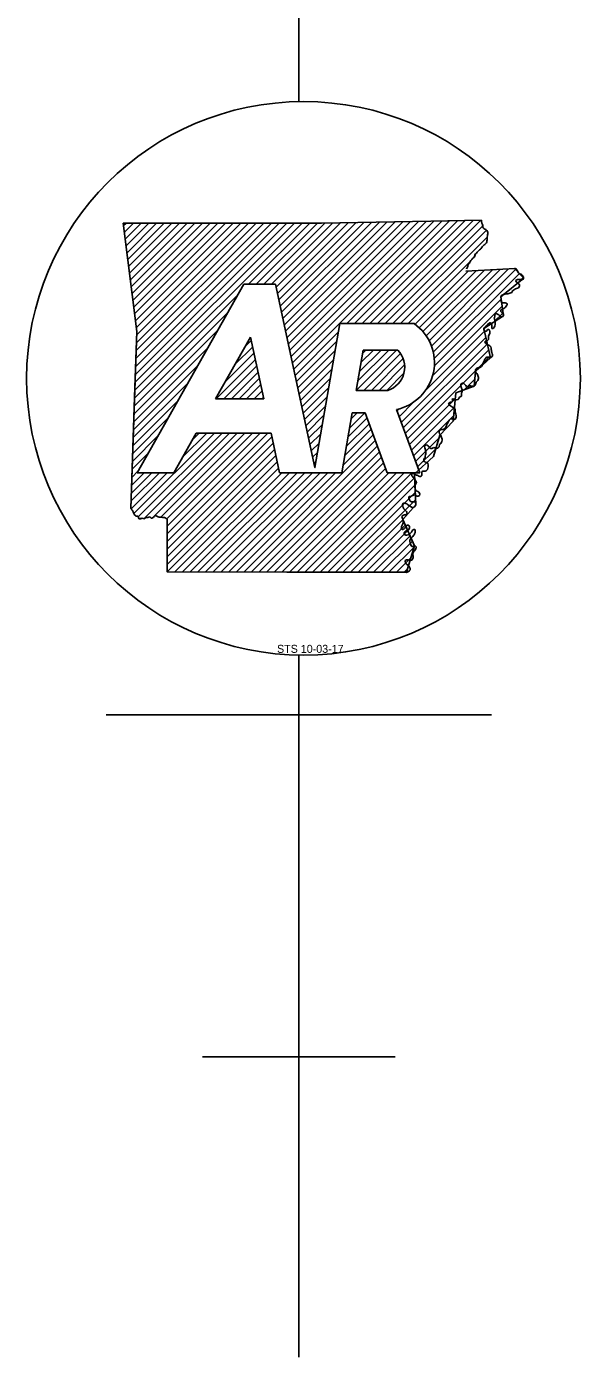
# Model space of a CAD drawing. Extents: x 1370130 to 1380143, y 377636 to 380256.
# Drawn here: x 1377791.3 to 1377833.4, y 379091.1 to 379192.1 of the extents above; entities that cross this region are included whole.
import ezdxf

# ---------------------------------------------------------------- set-up
doc = ezdxf.new("R2010")
doc.units = 0
for name, color, linetype in [('R_Draft', 7, 'Continuous'), ('R_Exist Surface', 7, 'Continuous'), ('R_Water Annot', 7, 'Continuous')]:
    doc.layers.add(name, color=color, linetype=linetype)

# ---------------------------------------------------------------- blocks, each defined once
blk = doc.blocks.new('NORTH ARROW VICINITY MAP')
at = {"layer": 'R_Draft'}
for p, q in [((0, 30.512), (0, 72.554)), ((-3.931, 21.495), (-1.338, 26.073)), ((-1.338, 26.073), (-0.568, 26.073)), ((0.996, 25.118), (2.796, 25.118)), ((-2.024, 23.292), (-1.176, 24.79)), ((1.557, 24.472), (2.402, 24.472)), ((-2.024, 23.292), (-0.855, 23.292)), ((1.386, 23.495), (2.158, 23.495)), ((2.366, 23.029), (2.932, 21.495)), ((1.604, 22.951), (1.292, 22.951)), ((2.142, 21.495), (1.604, 22.951)), ((-2.497, 22.456), (-3.041, 21.495)), ((-0.676, 22.456), (-2.497, 22.456)), ((-3.041, 21.495), (-3.931, 21.495)), ((1.038, 21.495), (-0.471, 21.495)), ((2.932, 21.495), (2.142, 21.495)), ((0, 0), (0, 17.063)), ((-4.681, 15.613), (4.68, 15.613)), ((-2.341, 7.3), (2.34, 7.3))]:
    blk.add_line(p, q, dxfattribs=at)
for points in [[(-4.267, 27.557), (-1.704, 27.556), (0.548, 27.561), (3.201, 27.602), (4.431, 27.631)], [(-4.267, 27.558), (-1.703, 27.556), (0.547, 27.561), (3.201, 27.602), (4.431, 27.631)], [(-4.081, 20.621), (-3.939, 24.923), (-4.267, 27.558)], [(-3.984, 23.572), (-3.939, 24.923), (-4.267, 27.557)], [(5.237, 26.453), (5.459, 26.221), (4.905, 25.767), (4.965, 25.308), (4.491, 24.995), (4.653, 24.289), (4.287, 23.955), (4.255, 23.593), (3.81, 23.433), (3.741, 22.748), (3.421, 22.406), (3.267, 21.891), (2.802, 21.465), (2.837, 20.714), (2.521, 20.359), (2.809, 19.714), (2.609, 19.074)], [(4.051, 26.393), (5.254, 26.455)], [(4.051, 26.394), (5.254, 26.454)], [(-0.568, 26.073), (0.385, 21.618), (0.996, 25.118)], [(-1.176, 24.79), (-0.855, 23.292)], [(1.386, 23.495), (1.557, 24.472)], [(-4.081, 20.621), (-3.984, 23.572)], [(1.292, 22.951), (1.038, 21.495)], [(-0.471, 21.495), (-0.676, 22.456)], [(2.609, 19.074), (-3.201, 19.083), (-3.205, 20.366)], [(2.609, 19.073), (-3.201, 19.083), (-3.204, 20.366)]]:
    blk.add_lwpolyline(points, dxfattribs=at)
blk.add_ellipse((0.109, 23.787), major_axis=(6.725, 0), ratio=0.999976, dxfattribs=at)
for centre, major_axis, start_param, end_param in [((2.127, 24.167), (-1.163, 0), 1.777838, 4.099264), ((1.973, 24.06), (-0.595, 0), 1.887169, 3.90762)]:
    blk.add_ellipse(centre, major_axis=major_axis, ratio=0.999987, start_param=start_param, end_param=end_param, dxfattribs=at)
for points in [[(4.431, 27.631), (4.439, 27.561), (4.46, 27.525), (4.463, 27.458), (4.491, 27.429), (4.538, 27.401), (4.578, 27.355), (4.588, 27.302), (4.575, 27.246), (4.572, 27.183), (4.566, 27.129), (4.556, 27.081), (4.518, 27.041), (4.482, 27.013), (4.449, 26.98), (4.425, 26.944), (4.384, 26.907), (4.342, 26.866), (4.308, 26.832), (4.275, 26.788), (4.259, 26.739), (4.224, 26.703), (4.195, 26.671), (4.157, 26.628), (4.138, 26.587), (4.102, 26.537), (4.093, 26.49), (4.07, 26.452), (4.068, 26.445)], [(4.431, 27.631), (4.439, 27.561), (4.461, 27.525), (4.465, 27.458), (4.491, 27.43), (4.537, 27.401), (4.579, 27.355), (4.588, 27.301), (4.576, 27.246), (4.572, 27.184), (4.566, 27.13), (4.556, 27.081), (4.518, 27.041), (4.482, 27.013), (4.449, 26.979), (4.425, 26.944), (4.384, 26.906), (4.342, 26.867), (4.309, 26.832), (4.276, 26.787), (4.26, 26.738), (4.224, 26.703), (4.195, 26.672), (4.157, 26.629), (4.138, 26.586), (4.101, 26.537), (4.094, 26.489), (4.07, 26.451), (4.068, 26.445)], [(5.237, 26.453), (5.254, 26.454), (5.308, 26.398), (5.331, 26.35), (5.367, 26.323), (5.407, 26.309), (5.437, 26.272), (5.457, 26.232), (5.446, 26.197), (5.401, 26.194), (5.352, 26.187), (5.305, 26.188), (5.266, 26.155), (5.302, 26.114), (5.348, 26.073), (5.36, 26.031), (5.335, 25.99), (5.284, 25.968), (5.235, 25.948), (5.19, 25.911), (5.169, 25.874), (5.121, 25.858), (5.07, 25.844), (5.026, 25.839), (4.975, 25.829), (4.926, 25.805), (4.906, 25.765), (4.912, 25.707), (4.91, 25.644), (4.962, 25.624), (5.008, 25.622), (5.053, 25.599), (5.048, 25.564), (5.015, 25.519), (4.975, 25.484), (4.936, 25.467), (4.899, 25.433), (4.912, 25.399), (4.945, 25.379), (4.969, 25.342), (4.965, 25.309), (4.927, 25.285), (4.886, 25.294), (4.855, 25.334), (4.821, 25.346), (4.79, 25.36), (4.756, 25.34), (4.756, 25.294), (4.744, 25.245), (4.755, 25.209), (4.768, 25.158), (4.767, 25.12), (4.755, 25.065), (4.727, 25.01), (4.697, 24.993), (4.682, 25.053), (4.677, 25.102), (4.657, 25.131), (4.632, 25.132), (4.599, 25.109), (4.563, 25.072), (4.517, 25.032), (4.49, 24.993), (4.504, 24.944), (4.539, 24.932), (4.566, 24.94), (4.58, 24.972), (4.606, 24.976), (4.632, 24.927)], [(4.632, 24.927), (4.639, 24.882), (4.612, 24.833), (4.602, 24.784), (4.606, 24.734), (4.556, 24.707), (4.512, 24.675), (4.538, 24.637), (4.586, 24.603), (4.632, 24.576), (4.662, 24.549), (4.67, 24.485), (4.678, 24.443), (4.695, 24.385), (4.701, 24.346), (4.672, 24.299), (4.639, 24.289), (4.603, 24.299), (4.563, 24.303), (4.53, 24.272), (4.506, 24.227), (4.482, 24.182), (4.463, 24.145), (4.446, 24.103), (4.412, 24.055), (4.37, 24.048), (4.319, 24.035), (4.288, 24), (4.294, 23.941), (4.322, 23.902), (4.344, 23.853), (4.359, 23.81), (4.352, 23.756), (4.33, 23.716), (4.302, 23.692), (4.288, 23.642), (4.267, 23.603), (4.249, 23.591), (4.211, 23.594), (4.169, 23.602), (4.135, 23.599), (4.102, 23.582), (4.068, 23.592), (4.033, 23.631), (4.004, 23.66), (3.972, 23.67), (3.939, 23.653), (3.934, 23.6), (3.95, 23.547), (3.964, 23.474), (3.95, 23.43), (3.944, 23.356)], [(3.944, 23.356), (3.889, 23.314), (3.864, 23.27), (3.723, 23.283), (3.727, 23.233), (3.677, 23.207), (3.632, 23.175), (3.657, 23.137), (3.705, 23.102), (3.753, 23.075), (3.783, 23.049), (3.79, 22.983), (3.799, 22.942), (3.815, 22.884), (3.821, 22.845), (3.792, 22.798), (3.759, 22.788), (3.725, 22.8), (3.683, 22.802), (3.65, 22.771), (3.626, 22.727), (3.603, 22.681), (3.585, 22.644), (3.566, 22.602), (3.533, 22.554), (3.49, 22.547), (3.439, 22.535), (3.409, 22.5), (3.414, 22.441), (3.442, 22.402), (3.464, 22.352), (3.48, 22.31), (3.473, 22.256), (3.451, 22.215), (3.422, 22.191), (3.409, 22.141), (3.388, 22.103), (3.369, 22.091), (3.332, 22.095), (3.291, 22.102), (3.256, 22.099), (3.223, 22.081), (3.188, 22.093), (3.154, 22.13), (3.125, 22.159), (3.093, 22.17), (3.059, 22.153), (3.054, 22.1), (3.07, 22.047), (3.084, 21.973), (3.07, 21.93), (3.065, 21.855)], [(3.065, 21.855), (3.061, 21.853), (3.033, 21.817), (3.049, 21.761), (3.11, 21.74), (3.139, 21.686), (3.14, 21.638), (3.12, 21.573), (3.091, 21.542), (3.036, 21.53), (2.994, 21.522), (2.987, 21.449), (2.968, 21.413), (2.935, 21.402), (2.887, 21.425), (2.858, 21.438), (2.823, 21.453), (2.779, 21.478), (2.745, 21.474), (2.755, 21.405), (2.758, 21.402), (2.797, 21.349), (2.834, 21.308), (2.851, 21.259)], [(3.065, 21.855), (3.061, 21.853), (3.033, 21.817), (3.049, 21.761), (3.11, 21.74), (3.139, 21.686), (3.14, 21.638), (3.12, 21.573), (3.091, 21.542), (3.036, 21.53), (2.994, 21.522), (2.987, 21.449), (2.968, 21.413), (2.935, 21.402), (2.887, 21.425), (2.858, 21.438), (2.823, 21.453), (2.779, 21.478), (2.745, 21.474), (2.755, 21.405), (2.758, 21.402), (2.797, 21.349), (2.834, 21.308), (2.851, 21.259)], [(2.851, 21.259), (2.836, 21.222), (2.818, 21.159), (2.823, 21.105), (2.848, 21.06), (2.885, 21.034), (2.927, 20.998), (2.924, 20.942), (2.899, 20.922), (2.843, 20.935), (2.801, 20.955), (2.765, 20.944), (2.716, 20.92), (2.679, 20.914), (2.681, 20.838), (2.729, 20.785), (2.772, 20.785), (2.822, 20.778), (2.839, 20.721), (2.81, 20.673), (2.763, 20.65), (2.703, 20.679), (2.66, 20.709), (2.618, 20.737), (2.564, 20.751), (2.533, 20.746), (2.519, 20.679), (2.544, 20.619), (2.585, 20.577), (2.623, 20.523), (2.618, 20.483), (2.589, 20.473), (2.538, 20.461), (2.508, 20.446), (2.501, 20.433), (2.516, 20.379), (2.53, 20.321), (2.53, 20.275), (2.512, 20.236), (2.486, 20.172), (2.489, 20.131), (2.508, 20.111), (2.531, 20.117), (2.564, 20.139), (2.584, 20.165), (2.602, 20.197), (2.634, 20.223), (2.675, 20.2), (2.685, 20.151), (2.662, 20.108), (2.628, 20.088), (2.588, 20.072), (2.557, 20.038), (2.564, 19.996), (2.589, 19.974), (2.648, 19.986), (2.687, 20.004), (2.71, 20.024), (2.736, 20.052), (2.75, 20.08), (2.771, 20.108), (2.808, 20.116), (2.825, 20.093), (2.818, 20.038), (2.797, 19.987), (2.766, 19.945), (2.733, 19.915), (2.692, 19.85), (2.7, 19.79), (2.716, 19.739), (2.737, 19.702), (2.776, 19.709), (2.818, 19.715), (2.843, 19.694), (2.841, 19.649), (2.81, 19.606), (2.779, 19.565), (2.763, 19.509), (2.77, 19.468), (2.77, 19.433), (2.757, 19.392), (2.735, 19.37), (2.675, 19.371), (2.614, 19.378), (2.581, 19.359), (2.588, 19.306), (2.623, 19.266), (2.649, 19.245), (2.685, 19.201), (2.701, 19.164), (2.697, 19.133), (2.674, 19.104), (2.609, 19.073)], [(2.851, 21.259), (2.836, 21.222), (2.818, 21.159), (2.823, 21.105), (2.848, 21.06), (2.885, 21.034), (2.927, 20.998), (2.924, 20.942), (2.899, 20.922), (2.843, 20.935), (2.801, 20.955), (2.765, 20.944), (2.716, 20.92), (2.679, 20.914), (2.681, 20.838), (2.729, 20.785), (2.772, 20.785), (2.822, 20.778), (2.839, 20.721), (2.81, 20.673), (2.763, 20.65), (2.703, 20.679), (2.66, 20.709), (2.618, 20.737), (2.564, 20.751), (2.533, 20.746), (2.519, 20.679), (2.544, 20.619), (2.585, 20.577), (2.623, 20.523), (2.618, 20.483), (2.589, 20.473), (2.538, 20.461), (2.508, 20.446), (2.501, 20.433), (2.516, 20.379), (2.53, 20.321), (2.53, 20.275), (2.512, 20.236), (2.486, 20.172), (2.489, 20.131), (2.508, 20.111), (2.531, 20.117), (2.564, 20.139), (2.584, 20.165), (2.602, 20.197), (2.634, 20.223), (2.675, 20.2), (2.685, 20.151), (2.662, 20.108), (2.628, 20.088), (2.588, 20.072), (2.557, 20.038), (2.564, 19.996), (2.589, 19.974), (2.648, 19.986), (2.687, 20.004), (2.71, 20.024), (2.736, 20.052), (2.75, 20.08), (2.771, 20.108), (2.808, 20.116), (2.825, 20.093), (2.818, 20.038), (2.797, 19.987), (2.766, 19.945), (2.733, 19.915), (2.692, 19.85), (2.7, 19.79), (2.716, 19.739), (2.737, 19.702), (2.776, 19.709), (2.818, 19.715), (2.843, 19.694), (2.841, 19.649), (2.81, 19.606), (2.779, 19.565), (2.763, 19.509), (2.77, 19.468), (2.77, 19.433), (2.757, 19.392), (2.735, 19.37), (2.675, 19.371), (2.614, 19.378), (2.581, 19.359), (2.588, 19.306), (2.623, 19.266), (2.649, 19.245), (2.685, 19.201), (2.701, 19.164), (2.697, 19.133), (2.674, 19.104), (2.609, 19.073)], [(-3.204, 20.366), (-3.198, 20.363), (-3.228, 20.384), (-3.27, 20.404), (-3.316, 20.407), (-3.375, 20.415), (-3.424, 20.42), (-3.474, 20.453), (-3.527, 20.419), (-3.588, 20.393), (-3.623, 20.422), (-3.669, 20.402), (-3.701, 20.413), (-3.756, 20.374), (-3.809, 20.388), (-3.846, 20.378), (-3.894, 20.379), (-3.904, 20.433), (-3.95, 20.44), (-3.99, 20.463), (-4.016, 20.518), (-4.036, 20.562), (-4.081, 20.621)], [(-3.205, 20.366), (-3.198, 20.363), (-3.228, 20.384), (-3.27, 20.404), (-3.316, 20.407), (-3.374, 20.415), (-3.423, 20.42), (-3.474, 20.453), (-3.528, 20.418), (-3.588, 20.393), (-3.623, 20.422), (-3.669, 20.403), (-3.701, 20.412), (-3.756, 20.374), (-3.809, 20.388), (-3.847, 20.377), (-3.894, 20.379), (-3.904, 20.433), (-3.95, 20.441), (-3.989, 20.463), (-4.016, 20.518), (-4.035, 20.561), (-4.081, 20.621)]]:
    blk.add_spline(points, degree=3, dxfattribs=at)
at = {"layer": 'R_Water Annot'}
for p, q in [((-4.26, 27.5), (-4.202, 27.558)), ((-4.239, 27.335), (-4.016, 27.558)), ((-4.219, 27.17), (-3.83, 27.558)), ((-4.198, 27.004), (-3.645, 27.558)), ((-4.177, 26.839), (-3.459, 27.558)), ((-4.157, 26.674), (-3.273, 27.557)), ((-4.136, 26.509), (-3.087, 27.557)), ((-4.116, 26.343), (-2.902, 27.557)), ((-4.095, 26.178), (-2.716, 27.557)), ((-4.074, 26.013), (-2.53, 27.557)), ((-4.054, 25.848), (-2.345, 27.557)), ((-4.033, 25.682), (-2.159, 27.557)), ((-4.013, 25.517), (-1.973, 27.557)), ((-3.992, 25.352), (-1.787, 27.556)), ((-3.986, 23.5), (0.075, 27.56)), ((-3.98, 23.692), (-0.112, 27.56)), ((-3.973, 23.884), (-0.298, 27.559)), ((-3.972, 25.187), (-1.601, 27.557)), ((-3.967, 24.076), (-0.484, 27.559)), ((-3.96, 24.268), (-0.67, 27.559)), ((-3.954, 24.461), (-0.857, 27.558)), ((-3.951, 25.021), (-1.415, 27.557)), ((-3.948, 24.653), (-1.043, 27.558)), ((-3.941, 24.845), (-1.229, 27.557)), ((-1.226, 26.073), (0.261, 27.561)), ((-1.04, 26.073), (0.447, 27.561)), ((-0.855, 26.073), (0.635, 27.563)), ((-0.669, 26.073), (0.823, 27.565)), ((-0.553, 26.003), (1.012, 27.568)), ((-0.52, 25.85), (1.201, 27.571)), ((-0.488, 25.697), (1.39, 27.574)), ((-0.455, 25.544), (1.578, 27.577)), ((-0.422, 25.391), (1.767, 27.58)), ((-0.389, 25.238), (1.956, 27.583)), ((-0.356, 25.085), (2.145, 27.586)), ((-0.324, 24.932), (2.333, 27.589)), ((-0.291, 24.779), (2.522, 27.592)), ((-0.258, 24.626), (2.711, 27.595)), ((-0.225, 24.473), (2.9, 27.598)), ((-0.193, 24.32), (3.088, 27.601)), ((-0.16, 24.166), (3.278, 27.604)), ((-0.127, 24.013), (3.468, 27.609)), ((1.164, 25.118), (3.658, 27.613)), ((1.35, 25.118), (3.849, 27.617)), ((1.535, 25.118), (4.039, 27.622)), ((1.721, 25.118), (4.229, 27.626)), ((1.907, 25.118), (4.419, 27.631)), ((2.093, 25.118), (4.461, 27.486)), ((2.279, 25.118), (4.551, 27.39)), ((2.465, 25.118), (4.575, 27.228)), ((2.65, 25.118), (4.15, 26.618)), ((2.819, 25.102), (4.114, 26.396)), ((2.921, 25.017), (4.31, 26.406)), ((3.011, 24.922), (4.506, 26.416)), ((3.092, 24.816), (4.701, 26.426)), ((3.161, 24.7), (4.897, 26.436)), ((3.217, 24.571), (5.093, 26.446)), ((3.26, 24.427), (5.27, 26.437)), ((3.285, 24.267), (5.356, 26.338)), ((5.274, 26.07), (5.443, 26.239)), ((-3.992, 23.307), (-1.485, 25.815)), ((3.286, 24.082), (4.913, 25.708)), ((-3.999, 23.115), (-1.727, 25.387)), ((3.248, 23.857), (4.934, 25.544)), ((4.726, 25.15), (4.956, 25.38)), ((-4.005, 22.923), (-1.97, 24.958)), ((-0.094, 23.86), (0.96, 24.915)), ((3.086, 23.51), (4.506, 24.93)), ((-1.308, 24.557), (-1.158, 24.707)), ((-0.062, 23.707), (0.921, 24.69)), ((2.48, 22.718), (4.541, 24.779)), ((2.531, 22.583), (4.575, 24.628)), ((-4.011, 22.731), (-2.213, 24.53)), ((-1.793, 23.7), (-1.093, 24.4)), ((-1.55, 24.128), (-1.125, 24.553)), ((-0.029, 23.554), (0.882, 24.465)), ((1.387, 23.495), (2.365, 24.472)), ((1.425, 23.718), (2.179, 24.472)), ((1.465, 23.943), (1.993, 24.472)), ((1.504, 24.168), (1.808, 24.472)), ((1.543, 24.394), (1.622, 24.472)), ((1.573, 23.495), (2.468, 24.39)), ((1.759, 23.495), (2.531, 24.267)), ((2.581, 22.447), (4.61, 24.476)), ((2.631, 22.311), (4.645, 24.325)), ((-4.018, 22.539), (-2.455, 24.101)), ((-2.015, 23.292), (-1.06, 24.247)), ((-1.829, 23.292), (-1.027, 24.094)), ((-1.643, 23.292), (-0.994, 23.941)), ((0.004, 23.401), (0.842, 24.24)), ((0.037, 23.248), (0.803, 24.015)), ((1.945, 23.495), (2.566, 24.115)), ((-4.024, 22.346), (-2.698, 23.673)), ((-1.457, 23.292), (-0.961, 23.788)), ((-1.271, 23.292), (-0.929, 23.635)), ((0.069, 23.095), (0.764, 23.79)), ((2.131, 23.495), (2.55, 23.914)), ((4.01, 23.504), (4.27, 23.765)), ((-1.086, 23.292), (-0.896, 23.482)), ((-0.9, 23.292), (-0.863, 23.329)), ((0.102, 22.942), (0.725, 23.564)), ((0.135, 22.789), (0.686, 23.339)), ((2.681, 22.176), (3.796, 23.29)), ((-4.031, 22.154), (-2.94, 23.244)), ((0.168, 22.636), (0.646, 23.114)), ((2.38, 22.99), (2.437, 23.046)), ((2.43, 22.854), (2.784, 23.208)), ((2.731, 22.04), (3.775, 23.084)), ((-4.037, 21.962), (-3.183, 22.816)), ((0.2, 22.483), (0.607, 22.889)), ((0.233, 22.33), (0.568, 22.664)), ((1.148, 22.13), (1.702, 22.684)), ((1.188, 22.355), (1.652, 22.819)), ((1.227, 22.58), (1.598, 22.951)), ((1.266, 22.805), (1.412, 22.951)), ((2.781, 21.904), (3.754, 22.877)), ((-4.043, 21.77), (-3.425, 22.388)), ((-4.009, 20.503), (-2.056, 22.456)), ((-3.899, 20.427), (-1.87, 22.456)), ((-3.766, 20.375), (-1.685, 22.456)), ((-3.545, 20.41), (-1.499, 22.456)), ((-3.356, 20.413), (-1.313, 22.456)), ((-3.21, 20.373), (-1.127, 22.456)), ((-3.204, 20.008), (-0.755, 22.456)), ((-3.204, 20.193), (-0.941, 22.456)), ((-3.203, 19.822), (-0.658, 22.368)), ((-2.83, 21.868), (-2.242, 22.456)), ((-2.588, 22.296), (-2.428, 22.456)), ((0.266, 22.176), (0.529, 22.439)), ((1.07, 21.68), (1.803, 22.412)), ((1.109, 21.905), (1.753, 22.548)), ((2.831, 21.769), (3.401, 22.338)), ((-3.203, 19.637), (-0.625, 22.215)), ((-3.202, 19.452), (-0.592, 22.062)), ((-1.343, 19.08), (1.853, 22.277)), ((-1.158, 19.08), (1.903, 22.141)), ((-0.972, 19.08), (1.953, 22.005)), ((0.299, 22.023), (0.489, 22.214)), ((0.331, 21.87), (0.45, 21.989)), ((2.881, 21.633), (3.322, 22.073)), ((-4.05, 21.578), (-3.668, 21.959)), ((-3.202, 19.266), (-0.559, 21.909)), ((-3.199, 19.083), (-0.527, 21.756)), ((-0.787, 19.08), (2.003, 21.87)), ((-0.601, 19.079), (2.053, 21.734)), ((0.364, 21.717), (0.411, 21.764)), ((-4.079, 20.619), (-3.203, 21.495)), ((-4.075, 20.809), (-3.389, 21.495)), ((-4.069, 21.001), (-3.574, 21.495)), ((-4.062, 21.193), (-3.76, 21.495)), ((-4.056, 21.385), (-3.911, 21.531)), ((-3.013, 19.083), (-0.494, 21.603)), ((-2.828, 19.083), (-0.415, 21.495)), ((-2.642, 19.083), (-0.229, 21.495)), ((-2.457, 19.082), (-0.044, 21.495)), ((-2.271, 19.082), (0.142, 21.495)), ((-2.086, 19.082), (0.328, 21.495)), ((-1.9, 19.081), (0.514, 21.495)), ((-1.715, 19.081), (0.7, 21.495)), ((-1.529, 19.081), (0.886, 21.495)), ((-0.416, 19.079), (2.103, 21.598)), ((-0.23, 19.079), (2.186, 21.495)), ((-0.045, 19.078), (2.372, 21.495)), ((0.141, 19.078), (2.558, 21.495)), ((0.326, 19.078), (2.744, 21.495)), ((0.512, 19.077), (2.806, 21.372)), ((0.697, 19.077), (2.814, 21.194)), ((0.883, 19.077), (2.823, 21.017)), ((1.068, 19.077), (2.831, 20.839)), ((1.254, 19.076), (2.526, 20.348)), ((1.439, 19.076), (2.583, 20.22)), ((1.625, 19.076), (2.641, 20.091)), ((1.811, 19.075), (2.698, 19.963)), ((1.996, 19.075), (2.755, 19.834)), ((2.182, 19.075), (2.803, 19.696)), ((2.367, 19.074), (2.719, 19.426)), ((2.553, 19.074), (2.635, 19.157))]:
    blk.add_line(p, q, dxfattribs=at)
at = {"layer": 'R_Draft'}
blk.add_text('STS 10-03-17', height=0.19444, dxfattribs=at).set_placement((-0.534, 17.117))

msp = doc.modelspace()

# ---------------------------------------------------------------- block references
at = {"layer": 'R_Exist Surface', "xscale": 3.12499999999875, "yscale": 3.1249999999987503}
msp.add_blockref('NORTH ARROW VICINITY MAP', (1377812, 379091.08), dxfattribs=at)

doc.saveas('drawing.dxf')
